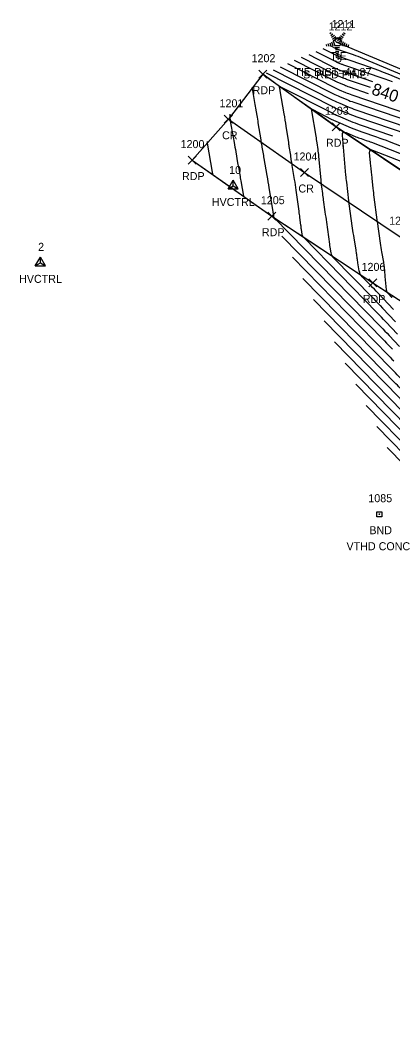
# Model space of a CAD drawing. Extents: x 1650836 to 1652450, y 332578 to 333908.
# Drawn here: x 1651721.6 to 1651814.5, y 332758.2 to 333007.6 of the extents above; entities that cross this region are included whole.
import ezdxf

# ---------------------------------------------------------------- set-up
doc = ezdxf.new("R2010")
doc.units = 0
for name, color, linetype in [('C_A', 7, 'Continuous'), ('C_C', 7, 'Continuous'), ('C_I', 7, 'Continuous'), ('CBP', 7, 'Continuous'), ('CPSM', 7, 'Continuous'), ('L_A', 7, 'Continuous'), ('L_C', 7, 'Continuous'), ('L_I', 7, 'Continuous'), ('LSOGCMA', 7, 'Continuous'), ('LSOGCMA_T', 7, 'Continuous'), ('LSOGCMI', 7, 'Continuous'), ('LSOGP', 7, 'Continuous'), ('LTC', 7, 'Continuous'), ('M_A', 7, 'Continuous'), ('M_C', 7, 'Continuous'), ('M_I', 7, 'Continuous'), ('MHBP', 7, 'Continuous'), ('P_A', 7, 'Continuous'), ('P_I', 7, 'Continuous'), ('P_TIC', 7, 'Continuous'), ('PET', 7, 'Continuous'), ('PRC', 7, 'Continuous')]:
    doc.layers.add(name, color=color, linetype=linetype)

msp = doc.modelspace()

# ---------------------------------------------------------------- linework, layer by layer
at = {"layer": 'CBP'}
for radius in [0.625, 0.0833]:
    msp.add_circle((1651800.95, 333002.62), radius, dxfattribs=at)
at = {"layer": 'CPSM'}
for p, q in [((1651773.55, 332965.43), (1651774.8, 332967.6)), ((1651776.05, 332965.43), (1651774.8, 332967.6)), ((1651774.8, 332966.15), (1651774.8, 332967.6)), ((1651773.55, 332965.43), (1651774.8, 332966.15)), ((1651773.55, 332965.43), (1651776.05, 332965.43)), ((1651774.8, 332966.15), (1651774.8, 332966.15)), ((1651774.8, 332966.15), (1651776.05, 332965.43)), ((1651725.41, 332946.22), (1651726.66, 332948.38)), ((1651725.41, 332946.22), (1651726.66, 332946.94)), ((1651727.91, 332946.22), (1651726.66, 332948.38)), ((1651726.66, 332946.94), (1651726.66, 332948.38)), ((1651726.66, 332946.94), (1651726.66, 332946.94)), ((1651726.66, 332946.94), (1651727.91, 332946.22)), ((1651725.41, 332946.22), (1651727.91, 332946.22))]:
    msp.add_line(p, q, dxfattribs=at)
at = {"layer": 'LSOGCMA'}
for points in [[(1651809.13, 332990.73), (1651803.38, 332992.69), (1651803.1, 332992.79), (1651802.83, 332992.89), (1651802.56, 332993), (1651802.29, 332993.11), (1651801.16, 332993.59), (1651800.92, 332993.69), (1651800.68, 332993.8), (1651800.44, 332993.91), (1651800.2, 332994.03), (1651791.9, 332998.25)], [(1651797.51, 332932.48), (1651816.37, 332913.18), (1651816.73, 332912.81), (1651817.09, 332912.43), (1651817.45, 332912.06), (1651817.81, 332911.68), (1651819.24, 332910.16), (1651819.59, 332909.88), (1651819.92, 332909.8), (1651820.23, 332909.93), (1651820.53, 332910.27), (1651823.27, 332914.43), (1651823.54, 332914.73), (1651823.82, 332914.85), (1651824.13, 332914.8), (1651824.35, 332914.65)]]:
    msp.add_lwpolyline(points, dxfattribs=at)
at = {"layer": 'LSOGCMI'}
for points in [[(1651800.86, 333002.02), (1651859.05, 332977.6), (1651861.64, 332976.53), (1651864.24, 332975.48), (1651866.85, 332974.46), (1651869.47, 332973.46), (1651883.76, 332968.08), (1651884.48, 332967.81), (1651885.21, 332967.53), (1651885.93, 332967.24), (1651886.65, 332966.96), (1651889.53, 332965.8), (1651890.25, 332965.51), (1651890.98, 332965.25), (1651891.71, 332965.01), (1651892.46, 332964.78), (1651908.32, 332960.11)], [(1651795.46, 332999.77), (1651800.43, 332997.24), (1651800.57, 332997.17), (1651800.72, 332997.1), (1651800.86, 332997.03), (1651801.01, 332996.97), (1651801.68, 332996.69), (1651801.85, 332996.62), (1651802.01, 332996.56), (1651802.17, 332996.49), (1651802.34, 332996.44), (1651812.73, 332992.89), (1651814.51, 332992.26)], [(1651797.23, 333000.53), (1651800.55, 332998.84), (1651800.64, 332998.8), (1651800.74, 332998.75), (1651800.83, 332998.71), (1651800.93, 332998.67), (1651801.38, 332998.47), (1651801.49, 332998.43), (1651801.6, 332998.39), (1651801.71, 332998.35), (1651801.82, 332998.31), (1651808.74, 332995.94), (1651809.93, 332995.53), (1651811.1, 332995.09), (1651812.28, 332994.63), (1651813.44, 332994.16), (1651846.91, 332980.12)], [(1651799.01, 333001.29), (1651800.66, 333000.45), (1651800.71, 333000.42), (1651800.76, 333000.4), (1651800.81, 333000.38), (1651800.85, 333000.36), (1651801.08, 333000.26), (1651801.13, 333000.24), (1651801.19, 333000.22), (1651801.24, 333000.2), (1651801.3, 333000.18), (1651804.75, 332999), (1651805.34, 332998.79), (1651805.93, 332998.58), (1651806.51, 332998.35), (1651807.09, 332998.11), (1651852.98, 332978.86)], [(1651788.35, 332996.73), (1651799.97, 332990.82), (1651800.3, 332990.66), (1651800.63, 332990.5), (1651800.97, 332990.34), (1651801.31, 332990.2), (1651802.89, 332989.53), (1651803.27, 332989.37), (1651803.65, 332989.23), (1651804.03, 332989.08), (1651804.42, 332988.95), (1651830.05, 332980.19)], [(1651808.61, 332989.21), (1651803.9, 332990.82), (1651803.57, 332990.94), (1651803.24, 332991.06), (1651802.91, 332991.19), (1651802.59, 332991.32), (1651801.23, 332991.89), (1651800.94, 332992.02), (1651800.65, 332992.15), (1651800.37, 332992.28), (1651800.09, 332992.42), (1651790.13, 332997.49)], [(1651793.68, 332999.01), (1651800.32, 332995.63), (1651800.51, 332995.54), (1651800.7, 332995.45), (1651800.89, 332995.36), (1651801.08, 332995.28), (1651801.99, 332994.9), (1651802.2, 332994.81), (1651802.42, 332994.72), (1651802.64, 332994.64), (1651802.86, 332994.56), (1651809.65, 332992.25)], [(1651783.02, 332994.45), (1651799.62, 332986.01), (1651800.1, 332985.77), (1651800.57, 332985.55), (1651801.05, 332985.33), (1651801.54, 332985.12), (1651803.8, 332984.16), (1651804.34, 332983.94), (1651804.88, 332983.73), (1651805.43, 332983.52), (1651805.98, 332983.33), (1651818.44, 332979.07)], [(1651784.8, 332995.21), (1651799.74, 332987.61), (1651800.16, 332987.4), (1651800.59, 332987.2), (1651801.02, 332987), (1651801.46, 332986.81), (1651803.5, 332985.95), (1651803.98, 332985.75), (1651804.47, 332985.56), (1651804.97, 332985.38), (1651805.46, 332985.2), (1651822.31, 332979.45)], [(1651786.57, 332995.97), (1651799.85, 332989.22), (1651800.23, 332989.03), (1651800.61, 332988.85), (1651801, 332988.67), (1651801.39, 332988.5), (1651803.19, 332987.74), (1651803.63, 332987.56), (1651804.06, 332987.39), (1651804.5, 332987.23), (1651804.94, 332987.08), (1651826.18, 332979.82)], [(1651779.55, 332990.89), (1651779.55, 332990.69), (1651779.55, 332990.65), (1651779.55, 332990.62), (1651779.55, 332990.59), (1651779.56, 332990.55), (1651780.07, 332987.48), (1651780.14, 332987.02), (1651780.22, 332986.55), (1651780.3, 332986.09), (1651780.38, 332985.63), (1651780.7, 332983.78), (1651780.78, 332983.31), (1651780.86, 332982.85), (1651780.94, 332982.38), (1651781.01, 332981.92), (1651781.69, 332977.67), (1651781.74, 332977.39), (1651781.78, 332977.12), (1651781.83, 332976.86), (1651781.87, 332976.59), (1651782.09, 332975.36), (1651782.12, 332975.16), (1651782.16, 332974.97), (1651782.19, 332974.77), (1651782.23, 332974.57), (1651782.36, 332973.78), (1651782.39, 332973.59), (1651782.43, 332973.39), (1651782.46, 332973.19), (1651782.49, 332972.99), (1651783.23, 332968.75), (1651783.36, 332967.97), (1651783.49, 332967.2), (1651783.62, 332966.42), (1651783.75, 332965.65), (1651784.72, 332959.74), (1651784.73, 332959.67), (1651784.75, 332959.6), (1651784.76, 332959.53), (1651784.77, 332959.46), (1651784.82, 332959.19), (1651784.83, 332959.12), (1651784.84, 332959.05), (1651784.85, 332958.98), (1651784.86, 332958.9), (1651784.91, 332958.49), (1651784.93, 332958.4), (1651784.97, 332958.32), (1651785.01, 332958.25), (1651785.07, 332958.18), (1651811.67, 332930.96), (1651812.19, 332930.42), (1651812.72, 332929.88), (1651813.24, 332929.33), (1651813.76, 332928.78), (1651816.32, 332926.05)], [(1651815.83, 332929.13), (1651812.95, 332932.2), (1651812.4, 332932.79), (1651811.84, 332933.37), (1651811.29, 332933.94), (1651810.73, 332934.52), (1651792.51, 332953.16), (1651792.33, 332953.37), (1651792.19, 332953.6), (1651792.09, 332953.86), (1651792.03, 332954.13), (1651791.87, 332955.26), (1651791.83, 332955.54), (1651791.79, 332955.82), (1651791.76, 332956.11), (1651791.72, 332956.39), (1651791.48, 332958.25), (1651791.43, 332958.65), (1651791.38, 332959.05), (1651791.32, 332959.46), (1651791.27, 332959.86), (1651790.56, 332965.14), (1651790.47, 332965.8), (1651790.37, 332966.46), (1651790.27, 332967.12), (1651790.16, 332967.78), (1651789.57, 332971.26), (1651789.53, 332971.5), (1651789.49, 332971.75), (1651789.46, 332971.99), (1651789.42, 332972.23), (1651789.24, 332973.48), (1651789.23, 332973.58), (1651789.21, 332973.69), (1651789.2, 332973.79), (1651789.18, 332973.89), (1651788.84, 332975.99), (1651788.8, 332976.24), (1651788.76, 332976.49), (1651788.72, 332976.73), (1651788.68, 332976.98), (1651788.05, 332981.1), (1651787.93, 332981.86), (1651787.81, 332982.63), (1651787.68, 332983.4), (1651787.56, 332984.17), (1651786.59, 332989.91), (1651786.58, 332989.96), (1651786.57, 332990.02), (1651786.56, 332990.07), (1651786.55, 332990.13), (1651786.52, 332990.34), (1651786.51, 332990.39), (1651786.5, 332990.45), (1651786.49, 332990.5), (1651786.48, 332990.55), (1651786.41, 332990.95), (1651786.41, 332991), (1651786.43, 332991.02), (1651786.46, 332991.03), (1651786.5, 332991.01), (1651799.51, 332984.4), (1651800.03, 332984.14), (1651800.55, 332983.89), (1651801.08, 332983.66), (1651801.61, 332983.42), (1651804.1, 332982.38), (1651804.69, 332982.13), (1651805.29, 332981.9), (1651805.9, 332981.67), (1651806.5, 332981.46), (1651814.57, 332978.7)], [(1651827.12, 332971.99), (1651813.86, 332977.17), (1651813.08, 332977.48), (1651812.29, 332977.77), (1651811.5, 332978.05), (1651810.7, 332978.33), (1651807.02, 332979.59), (1651806.36, 332979.82), (1651805.7, 332980.06), (1651805.05, 332980.32), (1651804.4, 332980.59), (1651801.69, 332981.73), (1651801.11, 332981.98), (1651800.53, 332982.24), (1651799.96, 332982.52), (1651799.39, 332982.8), (1651794.76, 332985.15), (1651794.59, 332985.21), (1651794.47, 332985.19), (1651794.42, 332985.09), (1651794.42, 332984.9), (1651795.44, 332978.61), (1651795.51, 332978.19), (1651795.57, 332977.78), (1651795.64, 332977.36), (1651795.7, 332976.95), (1651795.93, 332975.28), (1651795.99, 332974.87), (1651796.04, 332974.45), (1651796.09, 332974.03), (1651796.13, 332973.62), (1651796.7, 332967.59), (1651796.74, 332967.18), (1651796.78, 332966.76), (1651796.83, 332966.35), (1651796.88, 332965.94), (1651797.09, 332964.3), (1651797.15, 332963.88), (1651797.2, 332963.47), (1651797.26, 332963.06), (1651797.32, 332962.65), (1651797.74, 332959.66), (1651797.83, 332959.02), (1651797.92, 332958.39), (1651798.01, 332957.75), (1651798.1, 332957.12), (1651798.85, 332951.58), (1651798.88, 332951.41), (1651798.9, 332951.23), (1651798.93, 332951.05), (1651798.96, 332950.87), (1651799.19, 332949.42), (1651799.26, 332949.13), (1651799.37, 332948.86), (1651799.52, 332948.61), (1651799.71, 332948.38), (1651809.79, 332938.08), (1651810.38, 332937.47), (1651810.97, 332936.85), (1651811.55, 332936.24), (1651812.14, 332935.62), (1651815.34, 332932.21)], [(1651773.97, 332984.09), (1651773.95, 332983.45), (1651773.95, 332983.35), (1651773.95, 332983.26), (1651773.96, 332983.16), (1651773.97, 332983.07), (1651774.04, 332982.69), (1651774.05, 332982.6), (1651774.07, 332982.5), (1651774.08, 332982.41), (1651774.1, 332982.32), (1651775.06, 332977.01), (1651775.16, 332976.43), (1651775.27, 332975.84), (1651775.37, 332975.26), (1651775.47, 332974.68), (1651775.94, 332971.93), (1651776, 332971.55), (1651776.07, 332971.17), (1651776.14, 332970.79), (1651776.2, 332970.42), (1651776.47, 332968.91), (1651776.54, 332968.53), (1651776.6, 332968.15), (1651776.67, 332967.77), (1651776.73, 332967.4), (1651777.37, 332963.61)], [(1651814.85, 332935.29), (1651810.99, 332939.4), (1651810.54, 332939.87), (1651810.09, 332940.35), (1651809.64, 332940.81), (1651809.19, 332941.28), (1651807.06, 332943.45), (1651806.79, 332943.78), (1651806.57, 332944.13), (1651806.42, 332944.51), (1651806.32, 332944.93), (1651805.97, 332946.97), (1651805.93, 332947.23), (1651805.89, 332947.49), (1651805.85, 332947.75), (1651805.81, 332948.01), (1651805.66, 332949.04), (1651805.62, 332949.3), (1651805.58, 332949.56), (1651805.54, 332949.82), (1651805.5, 332950.08), (1651805.01, 332953.19), (1651804.91, 332953.79), (1651804.82, 332954.4), (1651804.73, 332955), (1651804.65, 332955.61), (1651803.82, 332961.68), (1651803.79, 332961.87), (1651803.77, 332962.06), (1651803.74, 332962.25), (1651803.72, 332962.44), (1651803.17, 332967.07), (1651803.12, 332967.52), (1651803.07, 332967.98), (1651803.02, 332968.43), (1651802.98, 332968.89), (1651802.12, 332978.83), (1651802.14, 332979.28), (1651802.3, 332979.55), (1651802.6, 332979.62), (1651803.04, 332979.5), (1651805.47, 332978.47), (1651805.79, 332978.34), (1651806.11, 332978.22), (1651806.43, 332978.1), (1651806.75, 332977.98), (1651808.05, 332977.54), (1651808.37, 332977.43), (1651808.7, 332977.31), (1651809.02, 332977.19), (1651809.34, 332977.07), (1651826.1, 332970.52)], [(1651769.77, 332968.95), (1651769.71, 332969.25), (1651769.71, 332969.28), (1651769.7, 332969.31), (1651769.7, 332969.34), (1651769.69, 332969.36), (1651769.67, 332969.48), (1651769.67, 332969.51), (1651769.66, 332969.54), (1651769.66, 332969.56), (1651769.65, 332969.59), (1651768.39, 332976.83), (1651768.38, 332976.88), (1651768.38, 332976.92), (1651768.37, 332976.97), (1651768.37, 332977.01), (1651768.38, 332977.28)], [(1651825.08, 332969.05), (1651809.69, 332975.06), (1651809.28, 332975.16), (1651808.99, 332975.09), (1651808.84, 332974.84), (1651808.82, 332974.41), (1651809.03, 332971.98), (1651809.06, 332971.66), (1651809.09, 332971.34), (1651809.13, 332971.01), (1651809.16, 332970.69), (1651809.32, 332969.41), (1651809.36, 332969.09), (1651809.39, 332968.77), (1651809.43, 332968.45), (1651809.46, 332968.13), (1651809.72, 332965.54), (1651809.77, 332965), (1651809.83, 332964.46), (1651809.9, 332963.92), (1651809.96, 332963.39), (1651810.71, 332957.73), (1651810.71, 332957.71), (1651810.71, 332957.69), (1651810.71, 332957.68), (1651810.71, 332957.66), (1651810.72, 332957.6), (1651810.72, 332957.59), (1651810.72, 332957.57), (1651810.73, 332957.55), (1651810.73, 332957.54), (1651810.75, 332957.39), (1651810.76, 332957.34), (1651810.76, 332957.31), (1651811.56, 332951.82), (1651811.64, 332951.29), (1651811.72, 332950.76), (1651811.81, 332950.23), (1651811.89, 332949.7), (1651812.33, 332947.11), (1651812.37, 332946.82), (1651812.42, 332946.52), (1651812.45, 332946.23), (1651812.49, 332945.93), (1651812.61, 332944.74), (1651812.64, 332944.44), (1651812.67, 332944.15), (1651812.7, 332943.85), (1651812.73, 332943.55), (1651813.04, 332940.2), (1651813.08, 332939.97), (1651813.16, 332939.76), (1651813.27, 332939.56), (1651813.41, 332939.38), (1651814.37, 332938.37), (1651814.38, 332938.36), (1651814.39, 332938.35), (1651814.4, 332938.36), (1651814.41, 332938.37), (1651814.45, 332938.43), (1651814.46, 332938.44), (1651814.47, 332938.45), (1651814.48, 332938.45), (1651814.5, 332938.44)], [(1651786.98, 332953.63), (1651812.61, 332927.41), (1651813.1, 332926.9), (1651813.59, 332926.39), (1651814.08, 332925.88), (1651814.57, 332925.36)], [(1651789.61, 332948.34), (1651813.55, 332923.85), (1651814.01, 332923.38), (1651814.47, 332922.9), (1651814.93, 332922.42)], [(1651826, 332916.45), (1651822.52, 332919.63), (1651822.13, 332919.89), (1651821.76, 332919.95), (1651821.42, 332919.81), (1651821.11, 332919.45), (1651819.4, 332916.86), (1651819.05, 332916.46), (1651818.68, 332916.31), (1651818.29, 332916.4), (1651817.88, 332916.72), (1651816.19, 332918.52), (1651815.77, 332918.97), (1651815.34, 332919.41), (1651814.92, 332919.85), (1651814.49, 332920.29), (1651792.25, 332943.05)], [(1651825.18, 332915.56), (1651823.49, 332917.1), (1651823.13, 332917.35), (1651822.79, 332917.4), (1651822.48, 332917.27), (1651822.19, 332916.94), (1651819.96, 332913.56), (1651819.64, 332913.2), (1651819.3, 332913.06), (1651818.94, 332913.14), (1651818.56, 332913.44), (1651817, 332915.1), (1651816.61, 332915.51), (1651816.22, 332915.92), (1651815.82, 332916.33), (1651815.43, 332916.74), (1651794.88, 332937.76)], [(1651800.14, 332927.19), (1651817.31, 332909.63), (1651817.64, 332909.29), (1651817.97, 332908.94), (1651818.3, 332908.6), (1651818.62, 332908.26), (1651819.92, 332906.87), (1651820.24, 332906.62), (1651820.54, 332906.55), (1651820.83, 332906.67), (1651821.1, 332906.97), (1651823.82, 332911.1)], [(1651825.54, 332909.52), (1651825.44, 332909.41), (1651821.66, 332903.68), (1651821.42, 332903.4), (1651821.16, 332903.3), (1651820.89, 332903.36), (1651820.61, 332903.59), (1651819.43, 332904.83), (1651819.14, 332905.15), (1651818.84, 332905.46), (1651818.55, 332905.76), (1651818.25, 332906.07), (1651802.78, 332921.9)], [(1651819.19, 332902.51), (1651805.41, 332916.61)], [(1651820.13, 332898.96), (1651808.04, 332911.32)], [(1651821.07, 332895.4), (1651810.68, 332906.04)], [(1651813.31, 332900.75), (1651822.01, 332891.85)]]:
    msp.add_lwpolyline(points, dxfattribs=at)
at = {"layer": 'LSOGP'}
msp.add_lwpolyline([(1651818.1, 332969.16), (1651812.24, 332973.09), (1651806.37, 332977.02), (1651800.5, 332980.95), (1651795.92, 332984.23), (1651791.34, 332987.52), (1651786.76, 332990.8), (1651782.19, 332994.09), (1651773.61, 332982.82), (1651764.55, 332972.62), (1651769.54, 332969.11), (1651774.53, 332965.61), (1651779.52, 332962.1), (1651784.51, 332958.6), (1651790.8, 332954.43), (1651797.1, 332950.26), (1651803.4, 332946.09), (1651809.7, 332941.93), (1651814.27, 332938.96), (1651818.84, 332935.99)], dxfattribs=at)
at = {"layer": 'LTC'}
for p, q in [((1651798.97, 333004.25), (1651799.33, 333004.51)), ((1651802.37, 333004.49), (1651802.79, 333004.19)), ((1651798.46, 333001.75), (1651798.67, 333001.1)), ((1651798.92, 333001.97), (1651799.19, 333001.13)), ((1651799.18, 333003.79), (1651799.71, 333004.17)), ((1651799.37, 333002.18), (1651799.7, 333001.16)), ((1651799.39, 333003.32), (1651800.1, 333003.83)), ((1651799.6, 333002.86), (1651800.48, 333003.49)), ((1651799.83, 333002.4), (1651800.84, 333003.14)), ((1651799.83, 333002.4), (1651800.22, 333001.21)), ((1651800.84, 333003.14), (1651801.84, 333002.41)), ((1651801.26, 333003.45), (1651802.07, 333002.86)), ((1651801.84, 333002.41), (1651801.45, 333001.21)), ((1651801.63, 333003.8), (1651802.31, 333003.3)), ((1651802.27, 333002.14), (1651801.94, 333001.1)), ((1651802, 333004.14), (1651802.55, 333003.75)), ((1651802.72, 333001.89), (1651802.43, 333001)), ((1651798.01, 333001.53), (1651798.16, 333001.06)), ((1651801.45, 333001.21), (1651800.22, 333001.21)), ((1651801.41, 333000.71), (1651800.26, 333000.71)), ((1651801.32, 333000.21), (1651800.34, 333000.21)), ((1651801.24, 332999.71), (1651800.41, 332999.71)), ((1651801.16, 332999.21), (1651800.48, 332999.21)), ((1651803.16, 333001.64), (1651802.93, 333000.91)), ((1651803.61, 333001.39), (1651803.42, 333000.81))]:
    msp.add_line(p, q, dxfattribs=at)
at = {"layer": 'MHBP'}
msp.add_lwpolyline([(1651810.72, 332884.73), (1651811.97, 332884.73), (1651811.97, 332883.48), (1651810.72, 332883.48)], close=True, dxfattribs=at)
msp.add_circle((1651811.34, 332884.11), 0.0833, dxfattribs=at)
at = {"layer": 'P_TIC'}
for points in [[(1651781.19, 332993.09), (1651783.19, 332995.09)], [(1651783.19, 332993.09), (1651781.19, 332995.09)], [(1651772.61, 332981.82), (1651774.61, 332983.82)], [(1651774.61, 332981.82), (1651772.61, 332983.82)], [(1651799.5, 332979.95), (1651801.5, 332981.95)], [(1651801.5, 332979.95), (1651799.5, 332981.95)], [(1651763.55, 332971.62), (1651765.55, 332973.62)], [(1651765.55, 332971.62), (1651763.55, 332973.62)], [(1651791.67, 332968.52), (1651793.67, 332970.52)], [(1651793.67, 332968.52), (1651791.67, 332970.52)], [(1651783.51, 332957.6), (1651785.51, 332959.6)], [(1651785.51, 332957.6), (1651783.51, 332959.6)], [(1651808.7, 332940.93), (1651810.7, 332942.93)], [(1651810.7, 332940.93), (1651808.7, 332942.93)]]:
    msp.add_lwpolyline(points, dxfattribs=at)
at = {"layer": 'PET'}
for points in [[(1651782.19, 332994.09), (1651800.5, 332980.95), (1651823.97, 332965.23), (1651861.09, 332941.31), (1651895.5, 332920.88), (1651932.1, 332899.88), (1651964.34, 332882.55), (1651997.08, 332865.29), (1652030.3, 332847.67), (1652049.55, 332837.67), (1652081.97, 332820.95), (1652121.03, 332800.4), (1652157.82, 332781.16), (1652191.94, 332763.08), (1652232.6, 332742.33), (1652251.93, 332731.59), (1652295.2, 332708.73), (1652345.73, 332682.34), (1652379.15, 332664.87), (1652402.11, 332652.83)], [(1651764.55, 332972.62), (1651784.51, 332958.6), (1651809.7, 332941.93), (1651846.26, 332918.16), (1651881.76, 332897.16), (1651918.12, 332876.64), (1651951.43, 332858.41), (1651975.3, 332845.48), (1652002.22, 332831.34), (1652037.17, 332813.42), (1652069.3, 332796.64), (1652107.43, 332776.54), (1652145.08, 332756.92), (1652175.23, 332740.23), (1652190.75, 332731.86), (1652206.57, 332723.52), (1652239.42, 332706.92), (1652282.4, 332684.37), (1652332.49, 332658.53), (1652365.54, 332641.17), (1652388.91, 332629.02)]]:
    msp.add_lwpolyline(points, dxfattribs=at)
at = {"layer": 'PRC'}
msp.add_lwpolyline([(1651773.61, 332982.82), (1651792.67, 332969.52), (1651816.54, 332953.47), (1651853.78, 332929.89), (1651888.83, 332909.03), (1651925.09, 332888.19), (1651957.73, 332870.48), (1651982.52, 332857.3), (1652019.65, 332837.68), (1652042.77, 332825.19), (1652076.05, 332808.31), (1652114.48, 332787.85), (1652150.94, 332769.1), (1652185.79, 332750.52), (1652225.78, 332729.89), (1652246.28, 332718.63), (1652288.71, 332696.53), (1652339, 332669.86), (1652372.56, 332652.7), (1652395.36, 332640.33)], dxfattribs=at)

# ---------------------------------------------------------------- texts
at = {"layer": 'C_A'}
for s, p in [('TIE', (1651799.03, 332997.62)), ('HVCTRL', (1651769.49, 332961.15)), ('HVCTRL', (1651721.36, 332941.94))]:
    msp.add_text(s, height=2, dxfattribs=at).set_placement(p)
at = {"layer": 'C_C'}
msp.add_text('TIE DIST=44.87', height=2, dxfattribs=at).set_placement((1651790.09, 332993.62))
at = {"layer": 'C_I'}
for s, p in [('1211', (1651799.39, 333005.62)), ('10', (1651773.81, 332969.15)), ('2', (1651726.1, 332949.94))]:
    msp.add_text(s, height=2, dxfattribs=at).set_placement(p)
at = {"layer": 'L_A'}
msp.add_text('S', height=2, dxfattribs=at).set_placement((1651800.17, 332997.04))
at = {"layer": 'L_C'}
msp.add_text('S. RED PINE', height=2, dxfattribs=at).set_placement((1651792.29, 332993.04))
at = {"layer": 'L_I'}
msp.add_text('1212', height=2, dxfattribs=at).set_placement((1651798.65, 333005.04))
at = {"layer": 'LSOGCMA_T'}
msp.add_text('840', height=3, rotation=341.1356, dxfattribs=at).set_placement((1651809.16, 332989.13))
at = {"layer": 'LTC'}
msp.add_text('.', height=1.04, rotation=270, dxfattribs=at).set_placement((1651800.72, 333002.15))
at = {"layer": 'M_A'}
msp.add_text('BND', height=2, dxfattribs=at).set_placement((1651808.83, 332879.11))
at = {"layer": 'M_C'}
msp.add_text('VTHD CONC', height=2, dxfattribs=at).set_placement((1651803.12, 332875.11))
at = {"layer": 'M_I'}
msp.add_text('1085', height=2, dxfattribs=at).set_placement((1651808.57, 332887.11))
at = {"layer": 'P_A'}
for s, p in [('RDP', (1651779.67, 332989.09)), ('CR', (1651772.05, 332977.82)), ('RDP', (1651797.99, 332975.95)), ('RDP', (1651762.03, 332967.62)), ('CR', (1651791.11, 332964.52)), ('RDP', (1651781.99, 332953.6)), ('RDP', (1651807.19, 332936.93))]:
    msp.add_text(s, height=2, dxfattribs=at).set_placement(p)
at = {"layer": 'P_I'}
for s, p in [('1202', (1651779.41, 332997.09)), ('1201', (1651771.41, 332985.82)), ('1203', (1651797.73, 332983.95)), ('1200', (1651761.69, 332975.62)), ('1204', (1651789.9, 332972.52)), ('1205', (1651781.73, 332961.6)), ('1207', (1651813.77, 332956.47)), ('1206', (1651806.88, 332944.93))]:
    msp.add_text(s, height=2, dxfattribs=at).set_placement(p)

doc.saveas('drawing.dxf')
